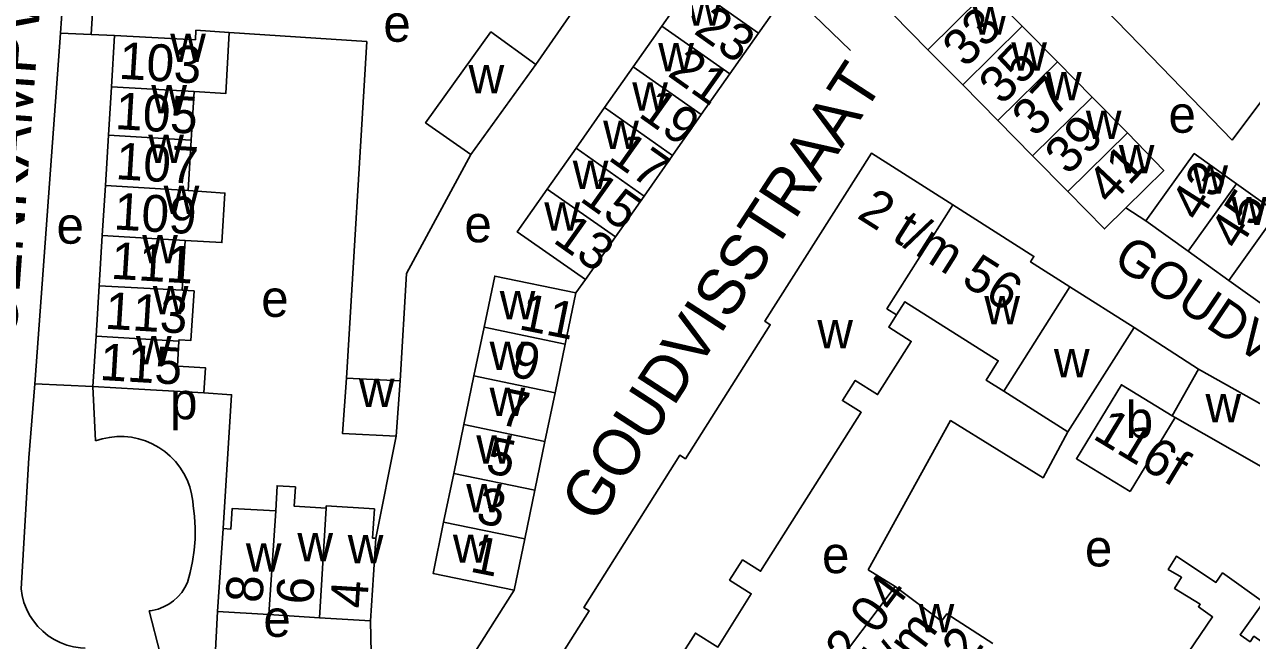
# Model space of a CAD drawing. Extents: x 159700 to 161346, y 381730 to 382922.
# Drawn here: x 160560.5 to 160693.5, y 382515.3 to 382582.1 of the extents above; entities that cross this region are included whole.
import ezdxf

# ---------------------------------------------------------------- set-up
doc = ezdxf.new("R2010")
doc.units = 0
for name, color, linetype in [('BLT_Basislijn', 7, 'Continuous'), ('BLT_Bebouwing', 7, 'Continuous'), ('BLT_Centroide', 7, 'Continuous'), ('BLT_Huisnummer', 7, 'Continuous'), ('BLT_Huisnummer_ tussenligend', 7, 'Continuous'), ('BLT_Huisnummer_reeks', 7, 'Continuous'), ('BLT_Onderdoorgang_en_onderverdeling', 7, 'Continuous'), ('BLT_Onderverdeling_panden', 7, 'Continuous'), ('BLT_Straatnaam', 7, 'Continuous'), ('BLT_Straatnaam_verkleind', 7, 'Continuous')]:
    doc.layers.add(name, color=color, linetype=linetype)

msp = doc.modelspace()

# ---------------------------------------------------------------- linework, layer by layer
at = {"layer": 'BLT_Basislijn'}
for p, q in [((160615.96, 382577.74), (160625.22, 382591.19)), ((160682.67, 382578.61), (160672.75, 382588.87)), ((160567.72, 382581), (160568.15, 382587.92)), ((160643.35, 382585.79), (160650.07, 382579.26)), ((160564.39, 382581.14), (160567.72, 382581)), ((160570.27, 382580.9), (160567.72, 382581)), ((160691.46, 382569.53), (160682.67, 382578.61)), ((160682.08, 382560.78), (160679.93, 382562.2)), ((160620.3, 382552.96), (160621.32, 382554.42)), ((160687.81, 382544.7), (160680.83, 382549.21)), ((160561.62, 382543.09), (160560.96, 382535.06)), ((160567.92, 382542.83), (160561.62, 382543.09)), ((160567.92, 382542.83), (160568.18, 382536.9)), ((160600.79, 382537.42), (160598.6, 382526.35)), ((160560.96, 382535.06), (160560.13, 382520.87)), ((160651.97, 382522.92), (160654.91, 382521.11)), ((160613.58, 382520.71), (160605.97, 382508.66)), ((160574.01, 382518.47), (160575.22, 382513.84)), ((160581.44, 382518.41), (160581.17, 382513.5)), ((160598.03, 382517.38), (160598.08, 382513.86))]:
    msp.add_line(p, q, dxfattribs=at)
for points in [[(160564.9, 382588.1), (160564.51, 382582.73), (160564.39, 382581.14)], [(160564.39, 382581.14), (160561.66, 382543.58), (160561.62, 382543.09)], [(160582.69, 382581.24), (160597.62, 382580.24), (160595.4, 382543.73)], [(160700, 382569.82), (160694.68, 382573.86), (160691.46, 382569.53)], [(160608.9, 382567.98), (160601.91, 382555.08), (160601.22, 382543.41)], [(160579.95, 382542.12), (160582.95, 382541.91), (160582.05, 382527.41)], [(160673.62, 382537.89), (160670.95, 382532.91), (160660.93, 382539.12), (160651.97, 382522.92)], [(160568.18, 382536.9), (160568.93, 382537.14), (160569.71, 382537.29), (160570.5, 382537.38), (160571.3, 382537.38), (160572.09, 382537.3), (160572.86, 382537.14), (160573.62, 382536.9), (160574.35, 382536.59), (160575.05, 382536.21), (160575.7, 382535.76), (160576.31, 382535.25), (160576.86, 382534.67), (160577.35, 382534.05), (160577.77, 382533.38), (160578.13, 382532.67), (160578.41, 382531.93), (160578.62, 382531.16), (160578.74, 382530.38), (160578.78, 382529.9)], [(160578.78, 382529.9), (160578.93, 382528.69), (160579, 382527.47), (160578.99, 382526.26), (160578.9, 382525.04), (160578.73, 382523.83), (160578.48, 382522.64), (160578.19, 382521.56)], [(160560.13, 382520.87), (160560.24, 382520.12), (160560.44, 382519.39), (160560.71, 382518.68), (160561.05, 382518.01), (160561.46, 382517.37), (160561.94, 382516.78), (160562.47, 382516.25), (160563.06, 382515.77), (160563.7, 382515.36), (160564.38, 382515.02), (160565.08, 382514.76), (160565.82, 382514.56), (160566.57, 382514.45), (160567.08, 382514.42)], [(160578.19, 382521.56), (160577.9, 382520.99), (160577.55, 382520.46), (160577.14, 382519.98), (160576.66, 382519.55), (160576.14, 382519.18), (160575.58, 382518.89), (160574.98, 382518.67), (160574.36, 382518.52), (160574.01, 382518.47)]]:
    msp.add_lwpolyline(points, dxfattribs=at)
at = {"layer": 'BLT_Bebouwing'}
for p, q in [((160629.6, 382581.92), (160632.71, 382586.36)), ((160664.9, 382585.74), (160668.69, 382581.9)), ((160658.46, 382579.36), (160654.67, 382583.22)), ((160626.5, 382577.5), (160629.6, 382581.92)), ((160668.69, 382581.9), (160672.51, 382578.03)), ((160569.93, 382575.33), (160570.27, 382580.9)), ((160570.27, 382580.9), (160579.03, 382580.42)), ((160640.09, 382581.15), (160636.99, 382576.73)), ((160662.24, 382575.53), (160658.46, 382579.36)), ((160608.9, 382567.98), (160615.96, 382577.74)), ((160672.51, 382578.03), (160676.27, 382574.22)), ((160623.39, 382573.07), (160626.5, 382577.5)), ((160636.99, 382576.73), (160633.89, 382572.31)), ((160569.6, 382570.07), (160569.93, 382575.33)), ((160666.05, 382571.66), (160662.24, 382575.53)), ((160578.9, 382574.82), (160578.58, 382569.53)), ((160676.27, 382574.22), (160680.09, 382570.33)), ((160620.31, 382568.67), (160623.39, 382573.07)), ((160633.89, 382572.31), (160630.78, 382567.89)), ((160669.81, 382567.85), (160666.05, 382571.66)), ((160569.27, 382564.63), (160569.6, 382570.07)), ((160578.58, 382569.53), (160578.24, 382564.08)), ((160617.19, 382564.23), (160620.31, 382568.67)), ((160630.78, 382567.89), (160627.68, 382563.48)), ((160673.64, 382563.96), (160669.81, 382567.85)), ((160568.93, 382559.18), (160569.27, 382564.63)), ((160691.94, 382564.79), (160696.33, 382561.65)), ((160627.68, 382563.48), (160624.58, 382559.07)), ((160686.7, 382557.48), (160682.08, 382560.78)), ((160568.59, 382553.74), (160568.93, 382559.18)), ((160624.58, 382559.07), (160621.32, 382554.42)), ((160577.91, 382558.64), (160577.58, 382553.27)), ((160691.08, 382554.33), (160686.7, 382557.48)), ((160568.26, 382548.29), (160568.59, 382553.74)), ((160695.49, 382551.18), (160691.08, 382554.33)), ((160620.3, 382552.96), (160619.14, 382547.41)), ((160673.86, 382553.62), (160680.83, 382549.21)), ((160609.24, 382543.96), (160610.34, 382549.25)), ((160680.83, 382549.21), (160673.62, 382537.89)), ((160567.92, 382542.83), (160568.26, 382548.29)), ((160619.14, 382547.41), (160618.04, 382542.14)), ((160684.95, 382539.64), (160687.81, 382544.7)), ((160687.81, 382544.7), (160698.08, 382538.92)), ((160595.4, 382543.73), (160601.22, 382543.41)), ((160601.22, 382543.41), (160600.79, 382537.42)), ((160608.15, 382538.68), (160609.24, 382543.96)), ((160618.04, 382542.14), (160616.94, 382536.85)), ((160673.62, 382537.89), (160666.68, 382542.3)), ((160685.26, 382539.45), (160680.4, 382531.43)), ((160607.05, 382533.39), (160608.15, 382538.68)), ((160616.94, 382536.85), (160615.84, 382531.56)), ((160605.95, 382528.1), (160607.05, 382533.39)), ((160615.84, 382531.56), (160614.74, 382526.27)), ((160582.05, 382527.41), (160581.44, 382518.41)), ((160614.74, 382526.27), (160613.58, 382520.71)), ((160581.44, 382518.41), (160586.99, 382518.07)), ((160586.99, 382518.07), (160592.5, 382517.72)), ((160592.5, 382517.72), (160598.03, 382517.38))]:
    msp.add_line(p, q, dxfattribs=at)
for points in [[(160635.96, 382590.98), (160643.35, 382585.79), (160640.09, 382581.15)], [(160582.69, 382581.24), (160582.33, 382574.6), (160578.9, 382574.82)], [(160579.03, 382580.42), (160579.09, 382581.47), (160582.69, 382581.24)], [(160615.96, 382577.74), (160611.08, 382581.28), (160604, 382571.44), (160608.9, 382567.98)], [(160680.09, 382570.33), (160684.04, 382566.25), (160679.93, 382562.2)], [(160614.65, 382507.25), (160621.74, 382518.47), (160621.15, 382518.85), (160631.56, 382535.36), (160632.17, 382534.97), (160641.37, 382549.51), (160640.78, 382549.89), (160652.34, 382568.13), (160661.16, 382562.52)], [(160682.08, 382560.78), (160687.34, 382568.08), (160691.94, 382564.79)], [(160578.24, 382564.08), (160582.23, 382563.8), (160581.9, 382558.43), (160577.91, 382558.64)], [(160621.32, 382554.42), (160613.93, 382559.58), (160617.19, 382564.23)], [(160679.93, 382562.2), (160677.62, 382559.92), (160673.64, 382563.96)], [(160661.16, 382562.52), (160669.96, 382556.92), (160669.59, 382556.33), (160673.86, 382553.62)], [(160610.34, 382549.25), (160611.49, 382554.79), (160620.3, 382552.96)], [(160578.88, 382553.19), (160578.55, 382547.81), (160577.26, 382547.89), (160577.25, 382547.75)], [(160577.58, 382553.27), (160578.88, 382553.19)], [(160666.68, 382542.3), (160664.77, 382543.51), (160666.1, 382545.61), (160655.97, 382552.01), (160655.07, 382550.59)], [(160655.07, 382550.59), (160654.22, 382549.24), (160656.66, 382547.7), (160653.01, 382541.94), (160650.59, 382543.47), (160649.2, 382541.28), (160651.23, 382540.01), (160640.32, 382522.76), (160638.36, 382524), (160636.96, 382521.81), (160639.3, 382520.32), (160635.69, 382514.54), (160633.26, 382516.06), (160629.58, 382510.27), (160631.61, 382509), (160625.97, 382500.08)], [(160577.25, 382547.75), (160577.08, 382545.02), (160580.11, 382544.84), (160579.95, 382542.12)], [(160600.79, 382537.42), (160594.97, 382537.73), (160595.4, 382543.73)], [(160680.4, 382531.43), (160674.56, 382534.98), (160679.44, 382543.01), (160684.95, 382539.64)], [(160579.95, 382542.12), (160572.91, 382542.54), (160567.92, 382542.83)], [(160698.08, 382538.92), (160694.61, 382534.14), (160685.26, 382539.45)], [(160587.77, 382529.31), (160587.89, 382532.04), (160589.88, 382531.92), (160589.75, 382529.82), (160593.2, 382529.6)], [(160593.2, 382529.6), (160593.22, 382529.85), (160598.44, 382529.53), (160598.24, 382526.37), (160598.6, 382526.35)], [(160587.77, 382529.31), (160583.02, 382529.58), (160582.89, 382527.35), (160582.05, 382527.41)], [(160613.58, 382520.71), (160604.8, 382522.54), (160605.95, 382528.1)], [(160598.03, 382517.38), (160598.35, 382522.37), (160598.6, 382526.35)], [(160700, 382500.26), (160699.14, 382500.86), (160698.47, 382500), (160695.22, 382502.29), (160695.24, 382502.55), (160694.52, 382503.06), (160691.21, 382505.39), (160693.77, 382509.04), (160686.72, 382514), (160689.34, 382517.82), (160687.8, 382518.92), (160687.99, 382519.18), (160685.21, 382520.9), (160685.97, 382522.12), (160684.52, 382522.96), (160685.42, 382524.39), (160689.69, 382521.56), (160690.42, 382522.58), (160694.85, 382519.42), (160692.32, 382515.87), (160693.4, 382515.11), (160693.82, 382515.71), (160700, 382511.36)], [(160647.57, 382511.33), (160654.91, 382521.11)], [(160654.91, 382521.11), (160659.93, 382517.35), (160660.53, 382518.15), (160665.51, 382514.92)]]:
    msp.add_lwpolyline(points, dxfattribs=at)
at = {"layer": 'BLT_Onderdoorgang_en_onderverdeling'}
msp.add_line((160666.68, 382542.3), (160673.86, 382553.62), dxfattribs=at)
msp.add_lwpolyline([(160661.16, 382562.52), (160654.02, 382551.25), (160655.07, 382550.59)], dxfattribs=at)
at = {"layer": 'BLT_Onderverdeling_panden'}
for p, q in [((160640.09, 382581.15), (160632.71, 382586.36)), ((160658.46, 382579.36), (160664.9, 382585.74)), ((160629.6, 382581.92), (160636.99, 382576.73)), ((160668.69, 382581.9), (160662.24, 382575.53)), ((160666.05, 382571.66), (160672.51, 382578.03)), ((160633.89, 382572.31), (160626.5, 382577.5)), ((160578.9, 382574.82), (160569.93, 382575.33)), ((160676.27, 382574.22), (160669.81, 382567.85)), ((160623.39, 382573.07), (160630.78, 382567.89)), ((160578.58, 382569.53), (160569.6, 382570.07)), ((160673.64, 382563.96), (160680.09, 382570.33)), ((160627.68, 382563.48), (160620.31, 382568.67)), ((160578.24, 382564.08), (160569.27, 382564.63)), ((160686.7, 382557.48), (160691.94, 382564.79)), ((160617.19, 382564.23), (160624.58, 382559.07)), ((160696.33, 382561.65), (160691.08, 382554.33)), ((160577.91, 382558.64), (160568.93, 382559.18)), ((160577.58, 382553.27), (160568.59, 382553.74)), ((160610.34, 382549.25), (160619.14, 382547.41)), ((160577.25, 382547.75), (160568.26, 382548.29)), ((160618.04, 382542.14), (160609.24, 382543.96)), ((160684.95, 382539.64), (160685.26, 382539.45)), ((160608.15, 382538.68), (160616.94, 382536.85)), ((160615.84, 382531.56), (160607.05, 382533.39)), ((160586.99, 382518.07), (160587.77, 382529.31)), ((160592.5, 382517.72), (160593.2, 382529.6)), ((160605.95, 382528.1), (160614.74, 382526.27))]:
    msp.add_line(p, q, dxfattribs=at)

# ---------------------------------------------------------------- texts
at = {"layer": 'BLT_Centroide'}
for s, p in [('w', (160632.3, 382581.95)), ('e', (160599.41, 382580.22)), ('w', (160663.31, 382580.99)), ('w', (160576.3, 382578.03)), ('w', (160629.22, 382577.01)), ('w', (160667.5, 382577.08)), ('w', (160608.65, 382574.61)), ('w', (160671.27, 382573.86)), ('w', (160574.25, 382572.44)), ('w', (160626.4, 382572.76)), ('w', (160675.59, 382569.67)), ('e', (160684.55, 382570.35)), ('w', (160623.25, 382568.57)), ('w', (160573.92, 382567.06)), ('w', (160679.16, 382565.96)), ('w', (160619.95, 382564.25)), ('w', (160687.14, 382563.73)), ('w', (160575.59, 382561.53)), ('w', (160691.35, 382560.32)), ('w', (160616.87, 382559.72)), ('e', (160563.97, 382558.31)), ('e', (160608.2, 382558.46)), ('w', (160573.26, 382556.19)), ('w', (160574.41, 382550.66)), ('e', (160586.17, 382550.37)), ('w', (160612.03, 382550.1)), ('w', (160664.58, 382549.56)), ('w', (160646.47, 382546.96)), ('w', (160572.58, 382545.22)), ('w', (160610.93, 382544.61)), ('w', (160672.13, 382543.8)), ('w', (160596.76, 382540.58)), ('p', (160576.29, 382539.26)), ('w', (160610.93, 382539.6)), ('w', (160688.56, 382538.94)), ('b', (160679.91, 382537.22)), ('w', (160609.49, 382534.45)), ('w', (160608.4, 382529.17)), ('w', (160584.5, 382522.73)), ('w', (160590.09, 382523.84)), ('w', (160595.55, 382523.62)), ('w', (160606.95, 382523.68)), ('e', (160675.49, 382523.29)), ('e', (160646.98, 382522.56)), ('w', (160657.46, 382516.15)), ('e', (160586.4, 382515.65))]:
    msp.add_text(s, height=4, dxfattribs=at).set_placement(p)
at = {"layer": 'BLT_Huisnummer'}
for s, rotation, p in [('103', 356.5108, (160570.66, 382576.22)), ('21', 324.6261, (160630.11, 382576.61)), ('35', 46.6261, (160666.53, 382573.23)), ('17', 324.6261, (160623.66, 382567.48)), ('107', 356.5127, (160570.31, 382565.32)), ('41', 46.6261, (160678.24, 382562.36)), ('43', 57.6261, (160687.87, 382560.54)), ('13', 324.6261, (160617.68, 382558.54)), ('111', 356.5102, (160569.8, 382554.52)), ('11', 348.6261, (160613.98, 382549.05)), ('115', 356.6295, (160568.58, 382543.53)), ('116f', 328.7803, (160676.21, 382537.24)), ('5', 348.6261, (160610.37, 382533.48)), ('1', 348.6261, (160608.69, 382522.75)), ('8', 86.1399, (160586.28, 382519.26)), ('4', 86.3886, (160597.64, 382518.67))]:
    msp.add_text(s, height=4, rotation=rotation, dxfattribs=at).set_placement(p)
at = {"layer": 'BLT_Huisnummer_ tussenligend'}
for s, rotation, p in [('23', 324.6261, (160632.95, 382581.2)), ('33', 46.6261, (160662.59, 382577.28)), ('37', 46.6261, (160670.12, 382569.74)), ('105', 356.5108, (160570.26, 382570.76)), ('19', 324.6261, (160626.94, 382572.19)), ('39', 46.6261, (160673.69, 382565.62)), ('15', 324.6261, (160620.58, 382563.03)), ('109', 356.5127, (160570.11, 382559.87)), ('45', 57.6261, (160692.12, 382557.46)), ('113', 356.5102, (160569.15, 382549.09)), ('9', 348.6261, (160613.02, 382543.96)), ('7', 348.6261, (160611.85, 382538.73)), ('3', 348.6261, (160609.33, 382528.06)), ('6', 86.3886, (160591.78, 382519.08))]:
    msp.add_text(s, height=4, rotation=rotation, dxfattribs=at).set_placement(p)
at = {"layer": 'BLT_Huisnummer_reeks'}
for s, rotation, p in [('2 t/m 56', 327.6261, (160650.64, 382561.19)), ('2 04', 53.1948, (160650.23, 382512.19)), ('t/m', 53.1948, (160655.24, 382510.54)), ('2 12', 53.1948, (160658.42, 382506.45))]:
    msp.add_text(s, height=4, rotation=rotation, dxfattribs=at).set_placement(p)
at = {"layer": 'BLT_Straatnaam'}
for s, height, rotation, p in [('HAGENKAMPWEG ZUID', 4.9999, 85.8442, (160558.88, 382538.42)), ('GOUDVISSTRAAT', 5, 56.9884, (160622.58, 382527.77))]:
    msp.add_text(s, height=height, rotation=rotation, dxfattribs=at).set_placement(p)
at = {"layer": 'BLT_Straatnaam_verkleind'}
msp.add_text('GOUDVISSTRAAT', height=4, rotation=326.0512, dxfattribs=at).set_placement((160678.34, 382556.13))

doc.saveas('drawing.dxf')
